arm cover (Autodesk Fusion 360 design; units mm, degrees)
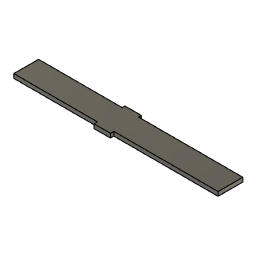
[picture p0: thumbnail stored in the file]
sketch "草图" plane through (0, 0, -20) normal (0, 0, -1) x axis (1, 0, 0)
  line L1 (-57.5, 9.5) -> (57.5, 9.5)
  line L2 (-57.5, -9.5) -> (-57.5, 9.5)
  line L3 (57.5, -9.5) -> (-57.5, -9.5)
  line L4 (57.5, 9.5) -> (57.5, -9.5)
  line L5 (-7.5, 8) -> (-7.5, 6.3532)
  line L6 (2.5, 8) -> (-7.5, 8)
  line L7 (2.5, 6.3532) -> (2.5, 8)
  line L8 (52.5, 6.3532) -> (2.5, 6.3532)
  line L9 (52.5, 5.5) -> (52.5, 6.3532)
  line L10 (52.5, -6.6468) -> (52.5, 5.5)
  line L11 (2.5, -6.6468) -> (52.5, -6.6468)
  line L12 (2.5, -8) -> (2.5, -6.6468)
  line L13 (-7.5, -8) -> (2.5, -8)
  line L14 (-7.5, -6.6468) -> (-7.5, -8)
  line L15 (-47.5, -6.6468) -> (-7.5, -6.6468)
  line L16 (-47.5, 6.3532) -> (-47.5, -6.6468)
  line L17 (-7.5, 6.3532) -> (-47.5, 6.3532)
  line L18 (-47.5, 6.3532) -> (-47.5, -6.6468)
  line L19 (52.5, -6.6468) -> (52.5, 6.3532)
  line L20 (-7.5, -8) -> (-7.5, -6.6468)
  line L21 (2.5, -8) -> (-7.5, -8)
  line L22 (2.5, -6.6468) -> (2.5, -8)
  line L23 (2.5, 8) -> (2.5, 6.3532)
  line L24 (-7.5, 8) -> (2.5, 8)
  line L25 (-7.5, 6.3532) -> (-7.5, 8)
  line L26 (2.5, -6.6468) -> (52.5, -6.6468)
  line L27 (-47.5, -6.6468) -> (-7.5, -6.6468)
  line L28 (-7.5, 6.3532) -> (-47.5, 6.3532)
  line L29 (52.5, 6.3532) -> (2.5, 6.3532)
  circle C1 centre (-51.5, 0) radius 1.5
  point P18 (-47.5, 6.3532)
  point P22 (-47.5, 6.3532)
  point P12 (52.5, -6.6468)
  point P20 (52.5, -6.6468)
  point P15 (-7.5, -8)
  point P26 (-7.5, -8)
  point P13 (2.5, -6.6468)
  point P24 (2.5, -6.6468)
  point P8 (2.5, 8)
  point P30 (2.5, 8)
  point P6 (-7.5, 6.3532)
  point P28 (-7.5, 6.3532)
  horizontal L26
  vertical L18
  horizontal L28
  vertical L19
  coincident P18 P22
  coincident P12 P20
  vertical L20
  horizontal L21
  vertical L22
  coincident P15 P26
  coincident P13 P24
  vertical L23
  horizontal L24
  vertical L25
  coincident P8 P30
  coincident P6 P28
  collinear L26 L27
  collinear L28 L29
extrude "拉伸2" new body sketch "草图" profile of L5 L6 L7 L8 L9 L10 L11 L12 L13 L14 L15 L16 L17 L27 L18 L29 L19 L20 L21 L22 L23 L24 L25 along normal blind 1
extrude "拉伸3" cut of existing geometry blind -1
extrude "拉伸4" cut of existing geometry blind -1
extrude "拉伸5" cut of existing geometry blind -1
extrude "拉伸6" cut of existing geometry blind -1
extrude "拉伸7" cut of existing geometry blind -0.5
extrude "拉伸8" cut of existing geometry blind -0.5
extrude "拉伸9" cut of existing geometry blind -0.5
extrude "拉伸10" cut of existing geometry blind -0.5
extrude "拉伸11" cut of existing geometry blind -0.5
extrude "拉伸12" cut of existing geometry blind -0.5
extrude "拉伸13" cut of existing geometry blind -0.5
extrude "拉伸14" cut of existing geometry blind -0.5
move "移动" TranslateX 0 TranslateY 0 TranslateZ 19.5
extrude "拉伸15" add of existing geometry blind 1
